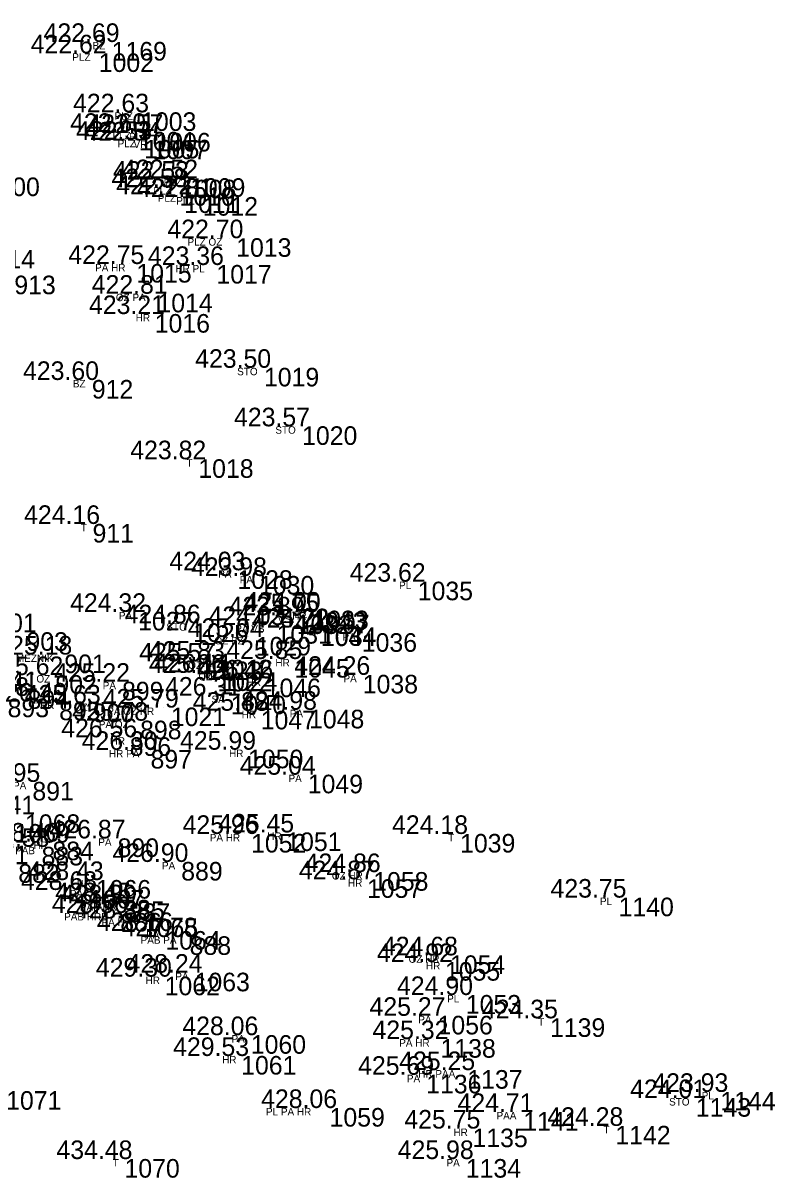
# Model space of a CAD drawing. Extents: x -639390 to -639075, y -1138747 to -1138358.
# Drawn here: x -639122.71 to -639092.35, y -1138695.49 to -1138648.89 of the extents above; entities that cross this region are included whole.
import ezdxf

# ---------------------------------------------------------------- set-up
doc = ezdxf.new("R2010")
doc.units = 0
for name, color, linetype in [('Vrstva 11', 7, 'Continuous'), ('Vrstva 12', 7, 'Continuous'), ('Vrstva 13', 7, 'Continuous'), ('Vrstva 57', 7, 'Continuous')]:
    doc.layers.add(name, color=color, linetype=linetype)

msp = doc.modelspace()

# ---------------------------------------------------------------- linework, layer by layer
at = {"layer": 'Vrstva 11'}
for p, q in [((-639119.41, -1138649.65), (-639119.41, -1138649.65)), ((-639119.93, -1138650.11), (-639119.93, -1138650.11)), ((-639118.22, -1138652.49), (-639118.22, -1138652.49)), ((-639118.31, -1138653.28), (-639118.31, -1138653.28)), ((-639117.64, -1138653.32), (-639117.64, -1138653.32)), ((-639118.1, -1138653.6), (-639118.1, -1138653.6)), ((-639117.76, -1138653.63), (-639117.76, -1138653.63)), ((-639116.61, -1138655.21), (-639116.61, -1138655.21)), ((-639116.24, -1138655.15), (-639116.24, -1138655.15)), ((-639116.67, -1138655.51), (-639116.67, -1138655.51)), ((-639116.48, -1138655.8), (-639116.48, -1138655.8)), ((-639115.73, -1138655.91), (-639115.73, -1138655.91)), ((-639114.38, -1138657.57), (-639114.38, -1138657.57)), ((-639118.41, -1138658.61), (-639118.41, -1138658.61)), ((-639115.18, -1138658.65), (-639115.18, -1138658.65)), ((-639117.56, -1138659.81), (-639117.56, -1138659.81)), ((-639117.67, -1138660.63), (-639117.67, -1138660.63)), ((-639113.26, -1138662.8), (-639113.26, -1138662.8)), ((-639120.21, -1138663.29), (-639120.21, -1138663.29)), ((-639111.72, -1138665.16), (-639111.72, -1138665.16)), ((-639115.91, -1138666.49), (-639115.91, -1138666.49)), ((-639120.18, -1138669.1), (-639120.18, -1138669.1)), ((-639114.33, -1138670.97), (-639114.33, -1138670.97)), ((-639113.46, -1138671.2), (-639113.46, -1138671.2)), ((-639107.05, -1138671.43), (-639107.05, -1138671.43)), ((-639118.34, -1138672.65), (-639118.34, -1138672.65)), ((-639111.35, -1138672.66), (-639111.35, -1138672.66)), ((-639111.26, -1138672.6), (-639111.26, -1138672.6)), ((-639116.12, -1138673.11), (-639116.12, -1138673.11)), ((-639111.94, -1138672.79), (-639111.94, -1138672.79)), ((-639112.75, -1138673.18), (-639112.75, -1138673.18)), ((-639110.96, -1138673.28), (-639110.96, -1138673.28)), ((-639110.95, -1138673.27), (-639110.95, -1138673.27)), ((-639109.31, -1138673.51), (-639109.31, -1138673.51)), ((-639113.59, -1138673.66), (-639113.59, -1138673.66)), ((-639121.32, -1138674.37), (-639121.32, -1138674.37)), ((-639112.03, -1138674.55), (-639112.03, -1138674.55)), ((-639115.55, -1138674.65), (-639115.55, -1138674.65)), ((-639115.16, -1138674.58), (-639115.16, -1138674.58)), ((-639121.68, -1138675.2), (-639121.68, -1138675.2)), ((-639118.99, -1138675.47), (-639118.99, -1138675.47)), ((-639115.14, -1138675.11), (-639115.14, -1138675.11)), ((-639114.95, -1138675.09), (-639114.95, -1138675.09)), ((-639113.19, -1138675.34), (-639113.19, -1138675.34)), ((-639109.27, -1138675.19), (-639109.27, -1138675.19)), ((-639121.53, -1138676.27), (-639121.53, -1138676.27)), ((-639120.17, -1138676.35), (-639120.17, -1138676.35)), ((-639114.6, -1138676.03), (-639114.6, -1138676.03)), ((-639117.02, -1138676.51), (-639117.02, -1138676.51)), ((-639113.39, -1138676.64), (-639113.39, -1138676.64)), ((-639111.44, -1138676.6), (-639111.44, -1138676.6)), ((-639118.26, -1138677.04), (-639118.26, -1138677.04)), ((-639118.68, -1138677.71), (-639118.68, -1138677.71)), ((-639117.84, -1138678.22), (-639117.84, -1138678.22)), ((-639113.9, -1138678.21), (-639113.9, -1138678.21)), ((-639122.61, -1138679.51), (-639122.61, -1138679.51)), ((-639111.49, -1138679.22), (-639111.49, -1138679.22)), ((-639121.8, -1138681.92), (-639121.8, -1138681.92)), ((-639119.17, -1138681.79), (-639119.17, -1138681.79)), ((-639113.78, -1138681.61), (-639113.78, -1138681.61)), ((-639112.36, -1138681.55), (-639112.36, -1138681.55)), ((-639105.34, -1138681.61), (-639105.34, -1138681.61)), ((-639122.24, -1138682.13), (-639122.24, -1138682.13)), ((-639116.6, -1138682.74), (-639116.6, -1138682.74)), ((-639108.85, -1138683.15), (-639108.85, -1138683.15)), ((-639120.32, -1138683.87), (-639120.32, -1138683.87)), ((-639120.05, -1138683.47), (-639120.05, -1138683.47)), ((-639109.1, -1138683.44), (-639109.1, -1138683.44)), ((-639118.94, -1138684.33), (-639118.94, -1138684.33)), ((-639098.94, -1138684.18), (-639098.94, -1138684.18)), ((-639119.06, -1138684.8), (-639119.06, -1138684.8)), ((-639118.72, -1138684.41), (-639118.72, -1138684.41)), ((-639118.15, -1138685.02), (-639118.15, -1138685.02)), ((-639117.24, -1138685.53), (-639117.24, -1138685.53)), ((-639116.26, -1138685.74), (-639116.26, -1138685.74)), ((-639105.75, -1138686.51), (-639105.75, -1138686.51)), ((-639105.95, -1138686.78), (-639105.95, -1138686.78)), ((-639117.27, -1138687.37), (-639117.27, -1138687.37)), ((-639116.06, -1138687.21), (-639116.06, -1138687.21)), ((-639105.11, -1138688.11), (-639105.11, -1138688.11)), ((-639106.25, -1138688.95), (-639106.25, -1138688.95)), ((-639101.71, -1138689.05), (-639101.71, -1138689.05)), ((-639113.79, -1138689.73), (-639113.79, -1138689.73)), ((-639106.13, -1138689.89), (-639106.13, -1138689.89)), ((-639114.18, -1138690.57), (-639114.18, -1138690.57)), ((-639106.71, -1138691.33), (-639106.71, -1138691.33)), ((-639105.05, -1138691.14), (-639105.05, -1138691.14)), ((-639094.83, -1138692.02), (-639094.83, -1138692.02)), ((-639110.61, -1138692.67), (-639110.61, -1138692.67)), ((-639095.82, -1138692.27), (-639095.82, -1138692.27)), ((-639102.79, -1138692.83), (-639102.79, -1138692.83)), ((-639104.84, -1138693.5), (-639104.84, -1138693.5)), ((-639099.07, -1138693.39), (-639099.07, -1138693.39)), ((-639118.89, -1138694.73), (-639118.89, -1138694.73)), ((-639105.11, -1138694.73), (-639105.11, -1138694.73))]:
    msp.add_line(p, q, dxfattribs=at)

# ---------------------------------------------------------------- texts
at = {"layer": 'Vrstva 12'}
for s, p in [('422.69 ', (-639121.879, -1138649.65)), ('422.62 ', (-639122.399, -1138650.11)), ('422.63 ', (-639120.689, -1138652.49)), ('422.60 ', (-639120.809, -1138653.28)), ('422.57 ', (-639120.109, -1138653.32)), ('422.53 ', (-639120.569, -1138653.6)), ('422.54 ', (-639120.229, -1138653.63)), ('422.53 ', (-639119.079, -1138655.21)), ('422.52 ', (-639118.709, -1138655.15)), ('422.58 ', (-639119.139, -1138655.51)), ('422.72 ', (-639118.949, -1138655.8)), ('422.81 ', (-639118.105, -1138655.91)), ('422.70 ', (-639116.879, -1138657.57)), ('422.75 ', (-639120.88, -1138658.61)), ('423.36 ', (-639117.666, -1138658.65)), ('422.81 ', (-639119.935, -1138659.81)), ('423.21 ', (-639120.045, -1138660.63)), ('423.50 ', (-639115.759, -1138662.8)), ('423.60 ', (-639122.709, -1138663.29)), ('423.57 ', (-639114.189, -1138665.16)), ('423.82 ', (-639118.379, -1138666.49)), ('424.16 ', (-639122.666, -1138669.1)), ('424.03 ', (-639116.799, -1138670.97)), ('423.98 ', (-639115.929, -1138671.2)), ('423.62 ', (-639109.519, -1138671.43)), ('424.32 ', (-639120.809, -1138672.65)), ('423.89 ', (-639114.409, -1138672.79)), ('425.75 ', (-639113.82, -1138672.66)), ('424.00 ', (-639113.759, -1138672.6)), ('424.86 ', (-639118.606, -1138673.11)), ('424.03 ', (-639115.219, -1138673.18)), ('425.72 ', (-639113.429, -1138673.28)), ('424.22 ', (-639113.419, -1138673.27)), ('425.01 ', (-639125.225, -1138673.47)), ('425.04 ', (-639116.059, -1138673.66)), ('423.97 ', (-639111.779, -1138673.51)), ('425.18 ', (-639123.789, -1138674.37)), ('425.57 ', (-639118.019, -1138674.65)), ('425.83 ', (-639117.629, -1138674.58)), ('425.85 ', (-639114.5, -1138674.55)), ('425.62 ', (-639124.149, -1138675.2)), ('425.86 ', (-639117.626, -1138675.11)), ('426.14 ', (-639117.419, -1138675.09)), ('424.26 ', (-639111.756, -1138675.19)), ('425.22 ', (-639121.459, -1138675.47)), ('426.16 ', (-639115.676, -1138675.34)), ('426.41 ', (-639125.175, -1138675.81)), ('426.31 ', (-639116.975, -1138676.03)), ('426.49 ', (-639123.999, -1138676.27)), ('425.63 ', (-639122.639, -1138676.35)), ('425.79 ', (-639119.489, -1138676.51)), ('425.88 ', (-639115.859, -1138676.64)), ('424.98 ', (-639113.909, -1138676.6)), ('425.78 ', (-639120.729, -1138677.04)), ('426.56 ', (-639121.166, -1138677.71)), ('426.30 ', (-639120.339, -1138678.22)), ('425.99 ', (-639116.369, -1138678.21)), ('426.95 ', (-639125.08, -1138679.51)), ('425.04 ', (-639113.959, -1138679.22)), ('428.41 ', (-639125.285, -1138680.82)), ('426.87 ', (-639121.639, -1138681.79)), ('425.96 ', (-639116.266, -1138681.61)), ('425.45 ', (-639114.83, -1138681.55)), ('424.18 ', (-639107.809, -1138681.61)), ('428.58 ', (-639124.709, -1138682.13)), ('428.40 ', (-639124.299, -1138681.92)), ('426.90 ', (-639119.099, -1138682.74)), ('429.71 ', (-639125.555, -1138682.83)), ('424.86 ', (-639111.336, -1138683.15)), ('428.43 ', (-639122.519, -1138683.47)), ('424.87 ', (-639111.569, -1138683.44)), ('428.68 ', (-639122.789, -1138683.87)), ('428.45 ', (-639121.41, -1138684.33)), ('428.39 ', (-639121.189, -1138684.41)), ('423.75 ', (-639101.41, -1138684.18)), ('428.56 ', (-639121.546, -1138684.8)), ('428.38 ', (-639120.619, -1138685.02)), ('428.16 ', (-639119.726, -1138685.53)), ('427.78 ', (-639118.729, -1138685.74)), ('424.92 ', (-639108.419, -1138686.78)), ('424.68 ', (-639108.219, -1138686.51)), ('429.30 ', (-639119.769, -1138687.37)), ('428.24 ', (-639118.529, -1138687.21)), ('424.90 ', (-639107.609, -1138688.11)), ('425.27 ', (-639108.719, -1138688.95)), ('424.35 ', (-639104.18, -1138689.05)), ('428.06 ', (-639116.276, -1138689.73)), ('425.32 ', (-639108.599, -1138689.89)), ('429.53 ', (-639116.649, -1138690.57)), ('425.25 ', (-639107.52, -1138691.14)), ('425.69 ', (-639109.179, -1138691.33)), ('423.93 ', (-639097.299, -1138692.02)), ('424.01 ', (-639098.195, -1138692.27)), ('428.06 ', (-639113.096, -1138692.67)), ('424.71 ', (-639105.165, -1138692.83)), ('424.28 ', (-639101.539, -1138693.39)), ('425.75 ', (-639107.31, -1138693.5)), ('434.48 ', (-639121.359, -1138694.73)), ('425.98 ', (-639107.579, -1138694.73))]:
    msp.add_text(s, height=0.75, dxfattribs=at).set_placement(p)
at = {"layer": 'Vrstva 13'}
for s, p in [(' 1169', (-639119.41, -1138650.4)), (' 1002', (-639119.93, -1138650.86)), (' 1003', (-639118.22, -1138653.24)), (' 1004', (-639118.31, -1138654.03)), (' 1006', (-639117.64, -1138654.07)), (' 1005', (-639118.1, -1138654.35)), (' 1007', (-639117.76, -1138654.38)), (' 1000', (-639124.54, -1138655.87)), (' 1008', (-639116.61, -1138655.96)), (' 1009', (-639116.24, -1138655.9)), (' 1010', (-639116.67, -1138656.26)), (' 1011', (-639116.48, -1138656.55)), (' 1012', (-639115.73, -1138656.66)), (' 1013', (-639114.38, -1138658.32)), (' 914', (-639124.18, -1138658.79)), (' 1015', (-639118.41, -1138659.36)), (' 1017', (-639115.18, -1138659.4)), (' 913', (-639123.34, -1138659.83)), (' 1014', (-639117.56, -1138660.56)), (' 1016', (-639117.67, -1138661.38)), (' 1019', (-639113.26, -1138663.55)), (' 912', (-639120.21, -1138664.04)), (' 1020', (-639111.72, -1138665.91)), (' 1018', (-639115.91, -1138667.24)), (' 911', (-639120.18, -1138669.85)), (' 1028', (-639114.33, -1138671.72)), (' 1030', (-639113.46, -1138671.95)), (' 1035', (-639107.05, -1138672.18)), (' 1027', (-639118.34, -1138673.4)), (' 1043', (-639111.35, -1138673.41)), (' 1033', (-639111.26, -1138673.35)), (' 1026', (-639116.12, -1138673.86)), (' 1032', (-639111.94, -1138673.54)), (' 903', (-639122.85, -1138674.22)), (' 1031', (-639112.75, -1138673.93)), (' 1044', (-639110.96, -1138674.03)), (' 1034', (-639110.95, -1138674.02)), (' 1036', (-639109.31, -1138674.26)), (' 1029', (-639113.59, -1138674.41)), (' 901', (-639121.32, -1138675.12)), (' 1045', (-639112.03, -1138675.3)), (' 1023', (-639115.55, -1138675.4)), (' 1042', (-639115.16, -1138675.33)), (' 908', (-639124.42, -1138676.04)), (' 902', (-639121.68, -1138675.95)), (' 899', (-639118.99, -1138676.22)), (' 1022', (-639115.14, -1138675.86)), (' 1024', (-639114.95, -1138675.84)), (' 1046', (-639113.19, -1138676.09)), (' 1038', (-639109.27, -1138675.94)), (' 894', (-639122.8, -1138676.56)), (' 893', (-639123.61, -1138676.9)), (' 895', (-639121.53, -1138677.02)), (' 900', (-639120.17, -1138677.1)), (' 1040', (-639114.6, -1138676.78)), (' 1021', (-639117.02, -1138677.26)), (' 1047', (-639113.39, -1138677.39)), (' 1048', (-639111.44, -1138677.35)), (' 898', (-639118.26, -1138677.79)), (' 896', (-639118.68, -1138678.46)), (' 897', (-639117.84, -1138678.97)), (' 1050', (-639113.9, -1138678.96)), (' 1049', (-639111.49, -1138679.97)), (' 891', (-639122.61, -1138680.26)), (' 1068', (-639122.91, -1138681.57)), (' 1069', (-639123.33, -1138681.96)), (' 1051', (-639112.36, -1138682.3)), (' 884', (-639121.8, -1138682.67)), (' 890', (-639119.17, -1138682.54)), (' 1052', (-639113.78, -1138682.36)), (' 1039', (-639105.34, -1138682.36)), (' 883', (-639122.24, -1138682.88)), (' 882', (-639123.18, -1138683.58)), (' 889', (-639116.6, -1138683.49)), (' 1058', (-639108.85, -1138683.9)), (' 1067', (-639120.32, -1138684.62)), (' 1066', (-639120.05, -1138684.22)), (' 1057', (-639109.1, -1138684.19)), (' 885', (-639118.94, -1138685.08)), (' 1140', (-639098.94, -1138684.93)), (' 886', (-639119.06, -1138685.55)), (' 887', (-639118.72, -1138685.16)), (' 1065', (-639118.15, -1138685.77)), (' 1064', (-639117.24, -1138686.28)), (' 888', (-639116.26, -1138686.49)), (' 1054', (-639105.75, -1138687.26)), (' 1055', (-639105.95, -1138687.53)), (' 1062', (-639117.27, -1138688.12)), (' 1063', (-639116.06, -1138687.96)), (' 1053', (-639105.11, -1138688.86)), (' 1056', (-639106.25, -1138689.7)), (' 1139', (-639101.71, -1138689.8)), (' 1060', (-639113.79, -1138690.48)), (' 1138', (-639106.13, -1138690.64)), (' 1061', (-639114.18, -1138691.32)), (' 1136', (-639106.71, -1138692.08)), (' 1137', (-639105.05, -1138691.89)), (' 1071', (-639123.67, -1138692.74)), (' 1143', (-639095.82, -1138693.02)), (' 1144', (-639094.83, -1138692.77)), (' 1059', (-639110.61, -1138693.42)), (' 1141', (-639102.79, -1138693.58)), (' 1135', (-639104.84, -1138694.25)), (' 1142', (-639099.07, -1138694.14)), (' 1070', (-639118.89, -1138695.48)), (' 1134', (-639105.11, -1138695.48))]:
    msp.add_text(s, height=0.75, dxfattribs=at).set_placement(p)
at = {"layer": 'Vrstva 57'}
for s, p in [('BZ', (-639119.899, -1138649.95)), ('PLZ', (-639120.719, -1138650.41)), ('PLZ', (-639119.009, -1138652.79)), ('PLZ', (-639119.099, -1138653.58)), ('PLZ', (-639118.429, -1138653.62)), ('PLZ', (-639118.889, -1138653.9)), ('VR', (-639118.249, -1138653.93)), ('VR', (-639117.099, -1138655.51)), ('PLZ', (-639117.029, -1138655.45)), ('PLZ', (-639117.459, -1138655.81)), ('PLZ', (-639117.269, -1138656.1)), ('PLZ', (-639116.519, -1138656.21)), ('PLZ OZ', (-639116.069, -1138657.87)), ('PA HR', (-639119.799, -1138658.91)), ('HR PL', (-639116.555, -1138658.95)), ('OZ PA', (-639118.96, -1138660.11)), ('HR', (-639118.159, -1138660.93)), ('STO', (-639114.061, -1138663.1)), ('BZ', (-639120.699, -1138663.59)), ('STO', (-639112.521, -1138665.46)), ('T', (-639116.11, -1138666.79)), ('T', (-639120.38, -1138669.4)), ('PA', (-639114.83, -1138671.27)), ('PA', (-639113.96, -1138671.5)), ('PL', (-639107.525, -1138671.73)), ('PA', (-639118.84, -1138672.95)), ('HR', (-639111.839, -1138672.96)), ('BZ', (-639111.749, -1138672.9)), ('STO', (-639116.921, -1138673.41)), ('VS', (-639112.429, -1138673.09)), ('PA VS', (-639114.139, -1138673.48)), ('PA', (-639111.45, -1138673.57)), ('HR', (-639111.449, -1138673.58)), ('PA', (-639109.81, -1138673.81)), ('OZ BZ', (-639114.979, -1138673.96)), ('MEZNIK', (-639122.995, -1138674.67)), ('HR', (-639112.519, -1138674.85)), ('OZ', (-639116.039, -1138674.95)), ('HR', (-639115.649, -1138674.88)), ('OZ', (-639122.169, -1138675.5)), ('PA', (-639119.49, -1138675.77)), ('OZ', (-639115.629, -1138675.41)), ('HR', (-639115.439, -1138675.39)), ('HR', (-639113.679, -1138675.64)), ('PA', (-639109.77, -1138675.49)), ('HR', (-639122.019, -1138676.57)), ('OZ', (-639120.659, -1138676.65)), ('SA', (-639115.1, -1138676.33)), ('PA OZ HR', (-639119.309, -1138676.81)), ('HR', (-639113.879, -1138676.94)), ('PA', (-639111.94, -1138676.9)), ('PA OZ', (-639119.649, -1138677.34)), ('HR', (-639119.169, -1138678.01)), ('HR PA', (-639119.24, -1138678.52)), ('HR', (-639114.389, -1138678.51)), ('PA', (-639123.11, -1138679.81)), ('PA', (-639111.99, -1138679.52)), ('HR', (-639122.289, -1138682.22)), ('PA', (-639119.67, -1138682.09)), ('PA HR', (-639115.169, -1138681.91)), ('HR', (-639112.849, -1138681.85)), ('T', (-639105.54, -1138681.91)), ('PAB', (-639123.029, -1138682.43)), ('PA', (-639117.1, -1138683.04)), ('OZ HR', (-639110.239, -1138683.45)), ('PA', (-639120.82, -1138684.17)), ('HR', (-639120.539, -1138683.77)), ('HR', (-639109.589, -1138683.74)), ('HR', (-639119.429, -1138684.63)), ('PL', (-639099.415, -1138684.48)), ('PAB HRB', (-639121.049, -1138685.1)), ('PAB HR', (-639120.409, -1138684.71)), ('PA HR', (-639119.539, -1138685.32)), ('PAB PA', (-639117.96, -1138686.04)), ('PA', (-639117.74, -1138685.83)), ('OZ HR', (-639107.139, -1138686.81)), ('HR', (-639106.439, -1138687.08)), ('HR', (-639117.759, -1138687.67)), ('PA', (-639116.56, -1138687.51)), ('PL', (-639105.585, -1138688.41)), ('PA', (-639106.75, -1138689.25)), ('T', (-639101.91, -1138689.35)), ('PA', (-639114.29, -1138690.03)), ('PA HR', (-639107.519, -1138690.19)), ('HR', (-639114.669, -1138690.87)), ('PA', (-639107.21, -1138691.63)), ('HR PAA', (-639106.75, -1138691.44)), ('STO', (-639096.621, -1138692.57)), ('PL', (-639095.305, -1138692.32)), ('PL PA HR', (-639112.899, -1138692.97)), ('PAA', (-639103.59, -1138693.13)), ('HR', (-639105.329, -1138693.8)), ('T', (-639099.27, -1138693.69)), ('T', (-639119.09, -1138695.03)), ('PA', (-639105.61, -1138695.03))]:
    msp.add_text(s, height=0.3, dxfattribs=at).set_placement(p)

doc.saveas('drawing.dxf')
